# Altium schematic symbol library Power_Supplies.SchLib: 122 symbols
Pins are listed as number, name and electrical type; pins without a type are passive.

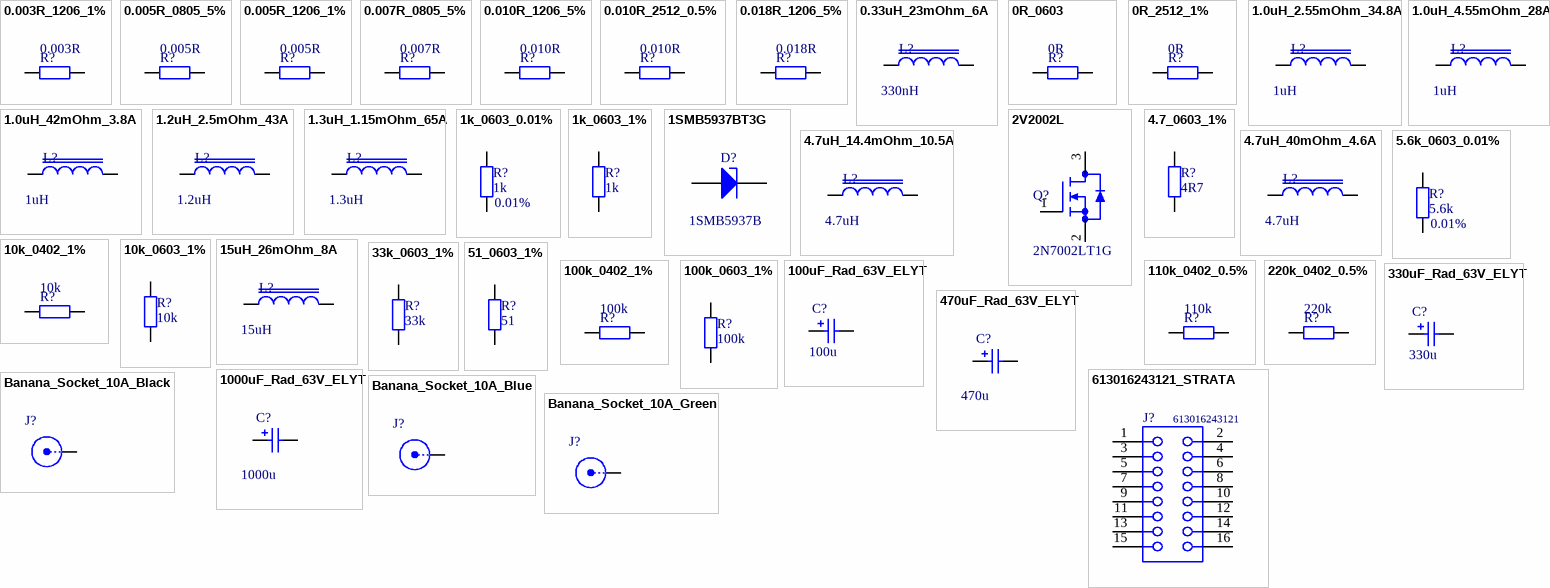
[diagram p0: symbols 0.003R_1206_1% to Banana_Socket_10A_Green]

## 0.003R_1206_1%
designator R?, comment value 0.003R  (hidden comment: WSL12063L000FEA18)
RES 0.003 OHM 1% 1/2W 1206, Vishay; Signature Author: Hukel; Value/Rating: 0.003R/1/2W; Substitution Allowed: Yes
footprint 1206_RES_MAX (1206, max dimensions from reflow soldering)
pins: 1, 2

## 0.005R_0805_5%
designator R?, comment value 0.005R  (hidden comment: ERJ-6LWJR005V)
RES 0.005 OHM 5% 1/2W 0805, Panasonic; Signature Author: Hukel; Value/Rating: 0.005R/1/2W; Substitution Allowed: Yes
footprint 0805_RES_MAX (0805, max dimensions from reflow soldering)
pins: 1, 2

## 0.005R_1206_1%
designator R?, comment value 0.005R  (hidden comment: WSL12065L000FEA18)
RES 0.005 OHM 1% 1/2W 1206, Vishay; Signature Author: Hukel; Value/Rating: 0.005R/1/2W; Substitution Allowed: Yes
footprint 1206_RES_MAX (1206, max dimensions from reflow soldering)
pins: 1, 2

## 0.007R_0805_5%
designator R?, comment value 0.007R  (hidden comment: ERJ-6LWJR007V)
RES 0.007 OHM 5% 1/2W 0805, Panasonic; Signature Author: Hukel; Value/Rating: 0.007R/1/2W; Substitution Allowed: Yes
footprint 0805_RES_MAX (0805, max dimensions from reflow soldering)
pins: 1, 2

## 0.010R_1206_5%
designator R?, comment value 0.010R  (hidden comment: ERJ-8CWJR010V)
RES 0.010 OHM 5% 1W 1206, Panasonic; Signature Author: Hukel; Value/Rating: 0.010R/1W; Substitution Allowed: Yes
footprint 1206_RES_MAX (1206, max dimensions from reflow soldering)
pins: 1, 2

## 0.010R_2512_0.5%
designator R?, comment value 0.010R  (hidden comment: PE2512DKM7W0R01L)
RES SMD 0.01 OHM 2W 2512; Yageo; Signature Author: Hukel; Rating: 1W; Tolerance: 0.5%; Value/Rating: 0.010R/1W; Substitution Allowed: Yes
footprint 2512_RES (2512, Reflow, YAGEO)
pins: 1, 2

## 0.018R_1206_5%
designator R?, comment value 0.018R  (hidden comment: ERJ-8CWJR018V)
RES 0.018 OHM 5% 1W 1206, Panasonic; Signature Author: Hukel; Value/Rating: 0.018R/1W; Substitution Allowed: Yes
footprint 1206_RES_MAX (1206, max dimensions from reflow soldering)
pins: 1, 2

## 0.33uH_23mOhm_6A
designator L?, comment value 330nH  (hidden comment: DFE252012PD-R33M)
0.33uH; 20%; 6A; 23mOhm; 2520; DFE252012PD-R33M; Murata; Signature Author: Hukel; Value/Rating: 330nH/6A; Substitution Allowed: Yes
footprint 2520_MURATA_IND_EVAL
pins: 1, 2

## 0R_0603
designator R?, comment value 0R  (hidden comment: Short)
RES SMD 0 OHM JUMPER 0603; Yageo; Signature Author: Hukel; Rating: 1W; Value/Rating: 0R/1W; Substitution Allowed: Yes
footprint 0603_RES (Chip Resistor, 2-Leads, Body 1.60x0.80mm, IPC Medium Density)
pins: 1, 2

## 0R_2512_1%
designator R?, comment value 0R  (hidden comment: RC2512JK-070RL)
RES SMD 0 OHM JUMPER 1W 2512; Yageo; Signature Author: Hukel; Value/Rating: 0R/1W; Substitution Allowed: Yes
footprint 0402_RES_MAX (0402, max dimensions from reflow soldering)
pins: 1, 2

## 1.0uH_2.55mOhm_34.8A
designator L?, comment value 1uH  (hidden comment: XAL7070-102MEC)
1.0uH; 20%; 34.8A; 2.55mOhm; 7.5x7.5x7mm ; XAL7070-102MEC; Coilcraft; Signature Author: Hukel; Value/Rating: 1uH/34.8A; Substitution Allowed: Yes
footprint XAL7070-102 (Precision Wire Wound Inductor, 2-Leads, Body 7.50x7.50mm, IPC Medium Density)
pins: 1, 2

## 1.0uH_4.55mOhm_28A
designator L?, comment value 1uH  (hidden comment: XAL7030-102MEC)
1.0uH; 20%; 28A; 4.55mOhm; 7.5x7.5x3.1mm ; XAL7030-102MEC; Coilcraft; Signature Author: Hukel; Value/Rating: 1uH/28A; Substitution Allowed: Yes
footprint XAL7030-102 (Precision Wire Wound Inductor, 2-Leads, Body 7.50x7.50mm, IPC Medium Density)
pins: 1, 2

## 1.0uH_42mOhm_3.8A
designator L?, comment value 1uH  (hidden comment: DFE252012PD-1R0M)
1.0uH; 20%; 3.8A; 42mOhm; 2520; DFE252012PD-1R0M; Murata; Signature Author: Hukel; Value/Rating: 1uH/3.8A; Substitution Allowed: Yes
footprint 2520_MURATA_IND_EVAL
pins: 1, 2

## 1.2uH_2.5mOhm_43A
designator L?, comment value 1.2uH  (hidden comment: XAL1060-122MED)
1.2uH; 20%; 43A; 2.50mOhm; 10x11.3x6mm ; XAL1060-122MED; Coilcraft; Signature Author: Hukel; Value/Rating: 1.2uH/43A; Substitution Allowed: Yes
footprint XAL1060-122 (XAL1060, Coilcraft)
pins: 1, 2

## 1.3uH_1.15mOhm_65A
designator L?, comment value 1.3uH  (hidden comment: XAL1580-132MEB)
1.3uH; 20%; 65A; 1.15mOhm; 15.2x16.2x8mm ; XAL1580-132MEB; Coilcraft; Signature Author: Hukel; Value/Rating: 1.3uH/65A; Substitution Allowed: Yes
footprint XAL1580-132
pins: 1, 2

## 1k_0603_0.01%
designator R?, comment value 1k  Tolerance: 0.01%  (hidden comment: PLT0603Z1001LBTS)
1k; 1/10W; 0.01%; 0603;  Vishay; Signature Author: Hukel; Value/Rating: 1k/1/10W; Substitution Allowed: Yes
simulation model RESISTOR (Resistor)
footprint 0603_RES (Chip Resistor, 2-Leads, Body 1.60x0.80mm, IPC Medium Density)
pins: 1, 2

## 1k_0603_1%
designator R?, comment value 1k  (hidden comment: RC0603FR-071KL)
1k; 1/10W; 1%; 0603; Yageo; Signature Author: Hukel; Value/Rating: 1k/1/10W; Substitution Allowed: Yes
simulation model RESISTOR (Resistor)
footprint 0603_RES (Chip Resistor, 2-Leads, Body 1.60x0.80mm, IPC Medium Density)
pins: 1, 2

## 1SMB5937BT3G
designator D?  value 1SMB5937B  (hidden comment: 1SMB5937BT3G)
1SMB5937B: 33 V, 3.0 W Zener Diode Voltage Regulator; SMB; ON Semiconductor; Signature Author: Hukel; Tolerance: 5%; Substitution Allowed: Yes; Rating: 33V/3W
footprint SMB (SMB, CASE403A-03, ISSUE J)
pins: 1 K, 2 A

## 2V2002L
designator Q?, comment 2N7002LT1G
60 V, 115 mA, 7.5 Ohm, N−Channel; SOT−23; ON Semiconductor; Signature Author: Hukel; Substitution Allowed: Yes
footprint SOT-23 (TO-236) (SOT-23 (TO-236), CASE 318-08, Issue AS)
pins: 1 G, 2 S, 3 D

## 4.7_0603_1%
designator R?, comment value 4R7  (hidden comment: RC0603FR-074R7L)
4.7; 1/10W; 1%; 0603; Yageo; Signature Author: Hukel; Value/Rating: 4R7/1/10W; Substitution Allowed: Yes
simulation model RESISTOR (Resistor)
footprint 0603_RES (Chip Resistor, 2-Leads, Body 1.60x0.80mm, IPC Medium Density)
pins: 1, 2

## 4.7uH_14.4mOhm_10.5A
designator L?, comment value 4.7uH  (hidden comment: XAL6060-472MEB)
4.7µH Shielded Wirewound Inductor 10.5A 14.4 mOhm Max; XAL6060-472MEB; Coilcraft; Signature Author: Hukel; Tolerance: ±20%; Value/Rating: 4.7uH/10.5A; Substitution Allowed: Yes
footprint XAL6060 (XAL6060 series Coilcraft inductors)
pins: 1, 2

## 4.7uH_40mOhm_4.6A
designator L?, comment value 4.7uH  (hidden comment: XEL4030-472MEB)
4.7µH Shielded Wirewound Inductor 4.6A 40 mOhm Max; XEL4030-472MEB; Coilcraft; Signature Author: Hukel; Tolerance: ±20%; Value/Rating: 4.7uH/4.6A; Substitution Allowed: Yes
footprint XEL4030 (XEL4030 series Colicraft inductors)
pins: 1, 2

## 5.6k_0603_0.01%
designator R?, comment value 5.6k  Tolerance: 0.01%  (hidden comment: PLT0603Z5621LBTS)
5.6k; 1/10W; 0.01%; 0603;  Vishay; Signature Author: Hukel; Value/Rating: 5.6k/1/10W; Substitution Allowed: Yes
simulation model RESISTOR (Resistor)
footprint 0603_RES (Chip Resistor, 2-Leads, Body 1.60x0.80mm, IPC Medium Density)
pins: 1, 2

## 10k_0402_1%
designator R?, comment value 10k  (hidden comment: RC0402FR-0710KL)
10k; 1/16W; 1%; 0402; Yageo; Signature Author: Hukel; Value/Rating: 10k/1/16W; Substitution Allowed: Yes
footprint 0402_RES_MAX (0402, max dimensions from reflow soldering)
pins: 1, 2

## 10k_0603_1%
designator R?, comment value 10k  (hidden comment: RC0603FR-0710KL)
10k; 1/10W; 1%; 0603; Yageo; Signature Author: Hukel; Value/Rating: 10k/1/10W; Substitution Allowed: Yes
simulation model RESISTOR (Resistor)
footprint 0603_RES (Chip Resistor, 2-Leads, Body 1.60x0.80mm, IPC Medium Density)
pins: 1, 2

## 15uH_26mOhm_8A
designator L?, comment value 15uH  (hidden comment: 7447709150)
15µH Shielded Wirewound Inductor 8A 26 mOhm Max; 7447709150; Wurth Electronics; Signature Author: Hukel; Tolerance: ±20%; Value/Rating: 15uH/8A; Substitution Allowed: Yes
footprint 1210_WE_IND (1210_WE_IND, Wuerth Inductor)
pins: 1, 2

## 33k_0603_1%
designator R?, comment value 33k  (hidden comment: RC0603FR-0733KL)
33k; 1/10W; 1%; 0603; Yageo; Signature Author: Hukel; Value/Rating: 33k/1/10W; Substitution Allowed: Yes
simulation model RESISTOR (Resistor)
footprint 0603_RES (Chip Resistor, 2-Leads, Body 1.60x0.80mm, IPC Medium Density)
pins: 1, 2

## 51_0603_1%
designator R?, comment value 51  (hidden comment: RC0603FR-0751RL)
51; 1/10W; 1%; 0603; Yageo; Signature Author: Hukel; Value/Rating: 51/1/10W; Substitution Allowed: Yes
simulation model RESISTOR (Resistor)
footprint 0603_RES (Chip Resistor, 2-Leads, Body 1.60x0.80mm, IPC Medium Density)
pins: 1, 2

## 100k_0402_1%
designator R?, comment value 100k  (hidden comment: RC0402FR-07100KL)
100k; 1/16W; 1%; 0402; Yageo; Signature Author: Hukel; Value/Rating: 100k/1/16W; Substitution Allowed: Yes
footprint 0402_RES (0402, Reflow, YAGEO)
pins: 1, 2

## 100k_0603_1%
designator R?, comment value 100k  (hidden comment: RC0603FR-07100KL)
100k; 1/10W; 1%; 0603; Yageo; Signature Author: Hukel; Value/Rating: 100k/1/10W; Substitution Allowed: Yes
simulation model RESISTOR (Resistor)
footprint 0603_RES (Chip Resistor, 2-Leads, Body 1.60x0.80mm, IPC Medium Density)
pins: 1, 2

## 100uF_Rad_63V_ELYT
designator C?, comment value 100u  (hidden comment: EEUFR1J101B)
100uF; 63 V; 20%; EEUFR1J101B; Panasonic; Signature Author: Zemanovic; Rating: 63V; Value/Rating: 100u/63V; Substitution Allowed: Yes
footprint Elyt_Radial_10X12.5 (Electrolytic Radial Aluminium capacitor 10 x 12.5 mm)
pins: 1, 2
1 alternate drawing of the same symbol

## 110k_0402_0.5%
designator R?, comment value 110k  (hidden comment: RC0402DR-07110KL)
110k; 1/16W; 0.5%; 0402; Yageo; Signature Author: Hukel; Value/Rating: 110k/1/16W; Substitution Allowed: Yes
footprint 0402_RES (0402, Reflow, YAGEO)
pins: 1, 2

## 220k_0402_0.5%
designator R?, comment value 220k  (hidden comment: RC0402DR-07220KL)
220k; 1/16W; 0.5%; 0402; Yageo; Signature Author: Hukel; Value/Rating: 220k/1/16W; Substitution Allowed: Yes
footprint 0402_RES_MAX (0402, max dimensions from reflow soldering)
pins: 1, 2

## 330uF_Rad_63V_ELYT
designator C?, comment value 330u  (hidden comment: EEUFR1J331B)
330uF; 63 V; 20%; EEUFR1J331B; Panasonic; Signature Author: Nagy; Rating: 63V; Value/Rating: 330u/63V; Substitution Allowed: Yes
footprint Elyt_Radial_10X12.5 (Electrolytic Radial Aluminium capacitor 10 x 12.5 mm)
pins: 1, 2
1 alternate drawing of the same symbol

## 470uF_Rad_63V_ELYT
designator C?, comment value 470u  (hidden comment: EUFR1J471)
470uF; 63V; 20%; ELYT; EUFR1J471; Panasonic; Signature Author: Zemanovic; Value/Rating: 470u/63V; Substitution Allowed: Yes
footprint Axial_D12.5_Pol
pins: 1, 2
1 alternate drawing of the same symbol

## 1000uF_Rad_63V_ELYT
designator C?, comment value 1000u  (hidden comment: EEU-FC1J102U)
1000uF; 63V; 20%; ELYT; EEU-FC1J102U; Panasonic; Signature Author: Nagy; Value/Rating: 1000u/63V; Substitution Allowed: Yes
footprint ELYT_RADIAL_16x31.5
pins: 1, 2
1 alternate drawing of the same symbol

## 613016243121_STRATA
designator J?, comment 613016243121
THT Angled Socket Header WR-PHD, Pitch 2.54 mm, Dual Row, 16 pins; Manufacturer: WUERTH ELECTRONIC; Pin Number: 16; Pitch: 2.54 mm; Gender: Female; Rated Current: 3 A; Working Voltage: 250 VAC; Withstanding Voltage: 500 VAC; Contact Resistance: 20 mOhm; Substitution Allowed: Yes; Signature Author: Hukel
footprint 613016243121_Strata (Socket Header, Pitch 2.54 mm, THT, Angled, dual row, 16p)
pins: 1, 2, 3, 4, 5, 6, 7, 8, 9, 10, 11, 12, 13, 14, 15, 16

## Banana_Socket_10A_Black
designator J?, comment 571-0100-01  (value not drawn)
10A; 4mm; TH; Black; 571-0100-01 ; DELTRON; Signature Author: Nagy; Substitution Allowed: Yes
footprint PCB Jack 4mm - black (DELTRON 571-0100-01)
pins: 1

## Banana_Socket_10A_Blue
designator J?, comment 571-0200-01  (value not drawn)
10A; 4mm; TH; Blue; 571-0200-01 ; DELTRON; Signature Author: Nagy; Substitution Allowed: Yes
footprint PCB Jack 4mm - blue (DELTRON 571-0200-01)
pins: 1

## Banana_Socket_10A_Green
designator J?, comment 571-0400-01  (value not drawn)
10A; 4mm; TH; Green; 571-0400-01 ; DELTRON; Signature Author: Nagy; Substitution Allowed: Yes
footprint PCB Jack 4mm - green (DELTRON 571-0400-01)
pins: 1

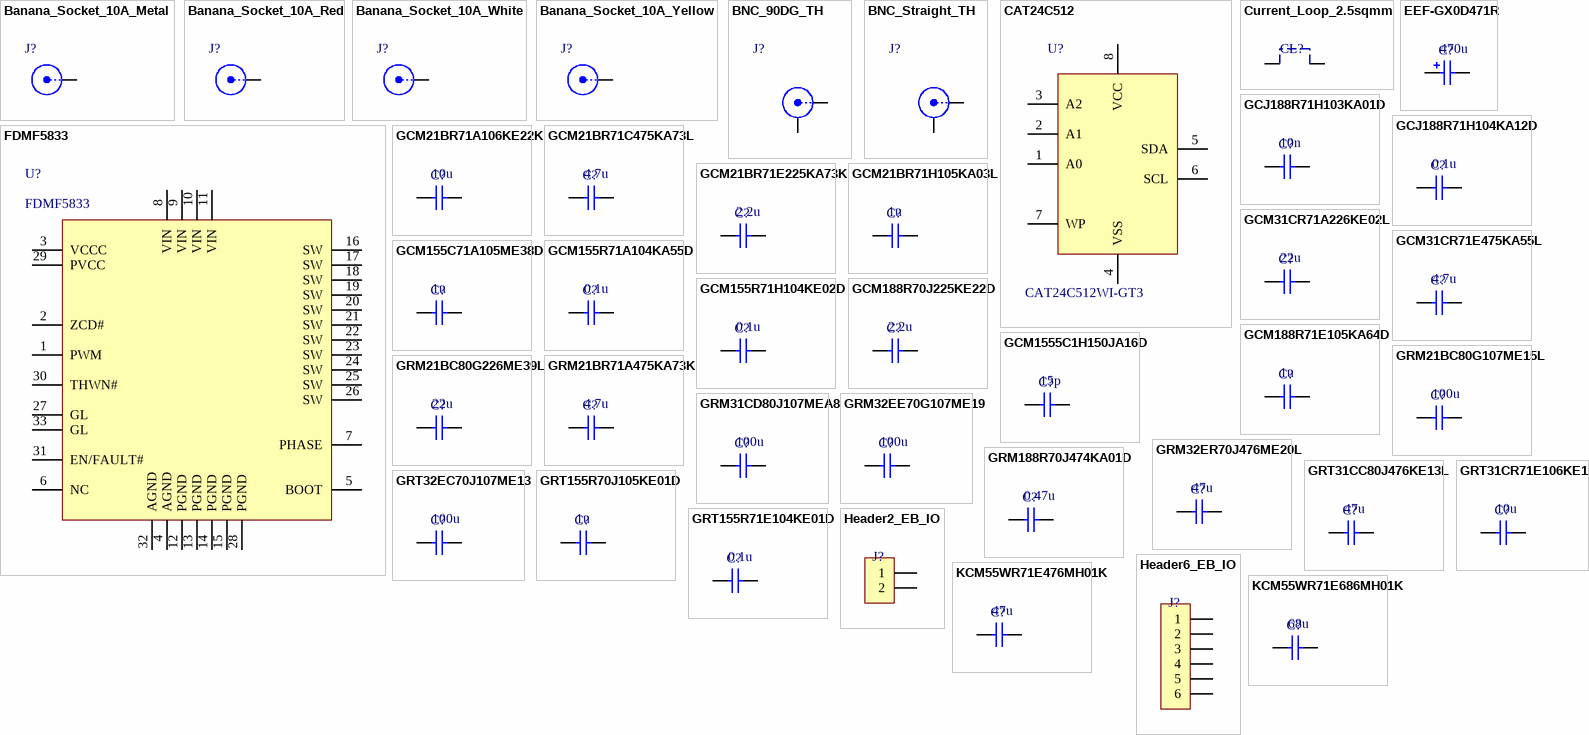
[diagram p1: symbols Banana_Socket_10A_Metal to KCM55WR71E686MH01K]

## Banana_Socket_10A_Metal
designator J?, comment SPC15459  (value not drawn)
10A; 4mm; TH; Metal; SPC15459 ; MULTICOMP; Signature Author: Nagy; Substitution Allowed: Yes
footprint PCB Banana - 1
pins: 1

## Banana_Socket_10A_Red
designator J?, comment 571-0500-01  (value not drawn)
10A; 4mm; TH; Red; 571-0500-01 ; DELTRON; Signature Author: Nagy; Substitution Allowed: Yes
footprint PCB Jack 4mm - red (DELTRON 571-0500-01)
pins: 1

## Banana_Socket_10A_White
designator J?, comment 571-0600-01  (value not drawn)
10A; 4mm; TH; White; 571-0600-01 ; DELTRON; Signature Author: Nagy; Substitution Allowed: Yes
footprint PCB Jack 4mm - white (DELTRON 571-0600-01)
pins: 1

## Banana_Socket_10A_Yellow
designator J?, comment 571-0700-01  (value not drawn)
10A; 4mm; TH; Yellow; 571-0700-01 ; DELTRON; Signature Author: Nagy; Substitution Allowed: Yes
footprint PCB Jack 4mm - yellow (DELTRON 571-0700-01)
pins: 1

## BNC_90DG_TH
designator J?, comment B6252HB-NPP3G-50  (value not drawn)
BNC 90 Angle Connector; 1.5GHz; B6252HB-NPP3G-50; Amphenol; Signature Author: Zemanovic; Substitution Allowed: Yes
footprint BNC_90DG_TH
pins: 1, 2

## BNC_Straight_TH
designator J?, comment R141426161  (value not drawn)
BNC Straight Connector; 1.5GHz; R141426161; Radial; Manufacturer: Radiall; Signature Author: Zemanovic; Substitution Allowed: Yes
footprint BNC_connector_Through_Hole_Vertical
pins: 1, 2

## CAT24C512
designator U?  value CAT24C512WI-GT3  (hidden comment: CAT24C512)
EEPROM Serial 512-Kb I2C; SO-8; ON Semiconductor; Signature Author: Hukel; Substitution Allowed: No
footprint SOIC-8 (SOIC-8 NB, CASE 751-7, Issue AK)
pins: 1 A0, 2 A1, 3 A2, 4 VSS, 5 SDA, 6 SCL, 7 WP, 8 VCC

## Current_Loop_2.5sqmm
designator CL?, comment Current Loop for 2.5 sqmm Cu wire  (value not drawn)
Current Loop Wire for Osciloscope Current Probe; Signature Author: Hukel; Rating: 1W; Tolerance: Wire Loop; Value/Rating: 0.005/1W; Substitution Allowed: Yes; Value: 0.005
footprint Current_Loop_2.5sqmm
pins: 1, 2

## EEF-GX0D471R
designator C?  value 470u  (hidden comment: EEF-GX0D471R)
470uF; 2V; Polymer Aluminum; 20%; 7343; EEF-GX0D471R; Panasonic; Signature Author: Hukel; Substitution Allowed: Yes; Value/Rating: 470u/2V
footprint 7343-20 (7343-20, Polymer Aluminum Electrolytic Capacitors, GX Series, ody 7.3x4.3x1.9 mm)
pins: 1, 2

## FDMF5833
designator U?
Smart Power Stage (SPS) Module with Integrated Thermal Warning and Thermal Shutdown
footprint PQFN31 5x5, 0.5P (DrMOS)
pins: 1 PWM, 2 ZCD#, 3 VCCC, 4 AGND, 5 BOOT, 6 NC, 7 PHASE, 8 VIN, 9 VIN, 10 VIN, 11 VIN, 12 PGND, 13 PGND, 14 PGND, 15 PGND, 16 SW, 17 SW, 18 SW, 19 SW, 20 SW, 21 SW, 22 SW, 23 SW, 24 SW, 25 SW, 26 SW, 27 GL, 28 PGND, 29 PVCC, 30 THWN#, 31 EN/FAULT#, 32 AGND, 33 GL

## GCJ188R71H103KA01D
designator C?  value 10n  (hidden comment: GCJ188R71H103KA01D)
10nF; 50V; X7R; 10%; 0603; GCJ188R71H103KA01D; Murata; Signature Author: Hukel; Substitution Allowed: Yes; Value/Rating: 10n/50V
footprint 0603_CAP (0603, MLCC, GRT Series, middle dimensions from reflow soldering, +/-0.15/+/-0.20 tolerances)
footprint 0603_CAP_MAX (0603, MLCC, GCM Series, max dimensions from reflow soldering)
pins: 1, 2

## GCJ188R71H104KA12D
designator C?  value 0.1u  (hidden comment: GCJ188R71H104KA12D)
0.1uF; 50V; X7R; 10%; 0603; GRM188R70J474KA01D; Murata; Signature Author: Hukel; Substitution Allowed: Yes; Value/Rating: 0.1u/50V
footprint 0603_CAP (0603, MLCC, GRT Series, middle dimensions from reflow soldering, +/-0.15/+/-0.20 tolerances)
footprint 0603_CAP_MAX (0603, MLCC, GCM Series, max dimensions from reflow soldering)
pins: 1, 2

## GCM21BR71A106KE22K
designator C?  value 10u  (hidden comment: GCM21BR71A106KE22K)
10uF; 10V; X7R; 10%; 0805; GCM21BR71A106KE22K; Murata; Signature Author: Hukel; Substitution Allowed: Yes; Value/Rating: 10u/10V
footprint 0805_CAP_MAX (0805, MLCC, GCM Series, max dimensions from reflow soldering)
pins: 1, 2

## GCM21BR71C475KA73L
designator C?  value 4.7u  (hidden comment: GCM21BR71C475KA73L)
4.7uF; 10V; X7R; 10%; 0805; GCM21BR71C475KA73L; Murata; Signature Author: Hukel; Substitution Allowed: Yes; Value/Rating: 4.7u/10V
footprint 0805_CAP_MAX (0805, MLCC, GCM Series, max dimensions from reflow soldering)
pins: 1, 2

## GCM21BR71E225KA73K
designator C?  value 2.2u  (hidden comment: GCM21BR71E225KA73K)
2.2uF; 25V; X7R; 10%; 0805; GCM21BR71E225KA73KL; Murata; Signature Author: Hukel; Substitution Allowed: Yes; Value/Rating: 2.2u/25V
footprint 0805_CAP_MAX (0805, MLCC, GCM Series, max dimensions from reflow soldering)
footprint 0805_CAP (0805, MLCC, GRT Series, middle dimensions from reflow soldering, +/-0.20 tolerances)
pins: 1, 2

## GCM21BR71H105KA03L
designator C?  value 1u  (hidden comment: GCM21BR71H105KA03L)
1uF; 50V; X7R; 10%; 0805; GCM21BR71H105KA03L; Murata; Signature Author: Hukel; Substitution Allowed: Yes; Value/Rating: 1u/50V
footprint 0805_CAP_MAX (0805, MLCC, GCM Series, max dimensions from reflow soldering)
footprint 0805_CAP (0805, MLCC, GRT Series, middle dimensions from reflow soldering, +/-0.20 tolerances)
pins: 1, 2

## GCM31CR71A226KE02L
designator C?  value 22u  (hidden comment: GCM31CR71A226KE02L)
22uF; 10V; X7R; 10%; 1206; GCM31CR71A226KE02L; Murata; Signature Author: Hukel; Substitution Allowed: Yes; Value/Rating: 22u/10V
footprint 1206_CAP_MAX (1206, MLCC, GCM Series, max dimensions from reflow soldering)
pins: 1, 2

## GCM31CR71E475KA55L
designator C?  value 4.7u  (hidden comment: GCM31CR71E475KA55L)
4.7uF; 25V; X7R; 10%; 1206; GCM31CR71E475KA55L; Murata; Signature Author: Hukel; Substitution Allowed: Yes; Value/Rating: 4.7u/25V
footprint 1206_CAP_MAX (1206, MLCC, GCM Series, max dimensions from reflow soldering)
pins: 1, 2

## GCM155C71A105ME38D
designator C?  value 1u  (hidden comment: GCM155C71A105ME38D)
1uF; 10V; X7S; 20%; 0402; GCM155C71A105ME38D; Murata; Signature Author: Hukel; Substitution Allowed: Yes; Value/Rating: 1u/10V
footprint 0402_CAP_MAX (0402, MLCC, GCM Series, max dimensions from reflow soldering)
footprint 0402_CAP (0402, MLCC, GRT Series, middle dimensions from reflow soldering, +/-0.15/+/-0.20 tolerances)
pins: 1, 2

## GCM155R71A104KA55D
designator C?  value 0.1u  (hidden comment: GCM155R71A104KA55D)
0.1uF; 10V; X7R; 10%; 0402; GCM155R71A104KA55D; Murata; Signature Author: Hukel; Substitution Allowed: Yes; Value/Rating: 0.1u/10V
footprint 0402_CAP_MAX (0402, MLCC, GCM Series, max dimensions from reflow soldering)
footprint 0402_CAP (0402, MLCC, GRT Series, middle dimensions from reflow soldering, +/-0.15/+/-0.20 tolerances)
pins: 1, 2

## GCM155R71H104KE02D
designator C?  value 0.1u  (hidden comment: GCM155R71H104KE02D)
0.1uF; 50V; X7R; 10%; 0402; GCM155R71H104KE02D; Murata; Signature Author: Hukel; Substitution Allowed: Yes; Value/Rating: 0.1u/50V
footprint 0402_CAP_MAX (0402, MLCC, GCM Series, max dimensions from reflow soldering)
footprint 0402_CAP (0402, MLCC, GRT Series, middle dimensions from reflow soldering, +/-0.15/+/-0.20 tolerances)
pins: 1, 2

## GCM188R70J225KE22D
designator C?  value 2.2u  (hidden comment: GCM188R70J225KE22D)
2.2uF; 6.3V; X7R; 10%; 0603; GCM188R70J225KE22D; Murata; Signature Author: Hukel; Substitution Allowed: Yes; Value/Rating: 2.2u/6.3V
footprint 0603_CAP_MAX (0603, MLCC, GCM Series, max dimensions from reflow soldering)
footprint 0603_CAP (0603, MLCC, GRT Series, middle dimensions from reflow soldering, +/-0.15/+/-0.20 tolerances)
pins: 1, 2

## GCM188R71E105KA64D
designator C?  value 1u  (hidden comment: GCM188R71E105KA64D)
1uF; 25V; X7R; 10%; 0603; GCM188R71E105KA64D; Murata; Signature Author: Hukel; Substitution Allowed: Yes; Value/Rating: 1u/25V
footprint 0603_CAP_MAX (0603, MLCC, GCM Series, max dimensions from reflow soldering)
footprint 0603_CAP (0603, MLCC, GRT Series, middle dimensions from reflow soldering, +/-0.15/+/-0.20 tolerances)
pins: 1, 2

## GCM1555C1H150JA16D
designator C?  value 15p  (hidden comment: GCM1555C1H150JA16D)
15pF; 50V; C0G; 5%; 0402; GCM1555C1H150JA16D; Murata; Signature Author: Hukel; Substitution Allowed: Yes; Value/Rating: 15p/50V
footprint 0402_CAP_MAX (0402, MLCC, GCM Series, max dimensions from reflow soldering)
footprint 0402_CAP (0402, MLCC, GRT Series, middle dimensions from reflow soldering, +/-0.15/+/-0.20 tolerances)
pins: 1, 2

## GRM21BC80G107ME15L
designator C?  value 100u  (hidden comment: GRM21BC80G107ME15L)
100uF; 4V; X6S; 20%; 0805; GRM21BC80G107ME15L; Murata; Signature Author: Hukel; Substitution Allowed: Yes; Value/Rating: 100u/4V
footprint 0805_CAP_MAX (0805, MLCC, GCM Series, max dimensions from reflow soldering)
footprint 0805_CAP (0805, MLCC, GRT Series, middle dimensions from reflow soldering, +/-0.20 tolerances)
pins: 1, 2

## GRM21BC80G226ME39L
designator C?  value 22u  (hidden comment: GRM21BC80G226ME39L)
22uF; 4V; X6S; 20%; 0805; GRM21BC80G226ME39L; Murata; Signature Author: Hukel; Substitution Allowed: Yes; Value/Rating: 22u/4V
footprint 0805_CAP_MAX (0805, MLCC, GCM Series, max dimensions from reflow soldering)
footprint 0805_CAP (0805, MLCC, GRT Series, middle dimensions from reflow soldering, +/-0.20 tolerances)
pins: 1, 2

## GRM21BR71A475KA73K
designator C?  value 4.7u  (hidden comment: GRM21BR71A475KA73K)
4.7uF; 10V; X7R; 10%; 0805; GRM21BR71A475KA73K;Murata; Signature Author: Hukel; Substitution Allowed: Yes; Value/Rating: 4.7u/10V
footprint 0805_CAP
pins: 1, 2

## GRM31CD80J107MEA8
designator C?  value 100u  (hidden comment: GRM31CD80J107MEA8)
100uF; 6.3V; X6T; 20%; 1206; GRM31CD80J107MEA8; Murata; Signature Author: Hukel; Substitution Allowed: Yes; Value/Rating: 100u/6.3V
footprint 1206_CAP_MAX (1206, MLCC, GCM Series, max dimensions from reflow soldering)
footprint 1206_CAP (1206_CAP, MLCC, GRT Series, middle dimensions from reflow soldering, +/-0.20 tolerances)
pins: 1, 2

## GRM32EE70G107ME19
designator C?  value 100u  (hidden comment: GRM32EE70G107ME19)
100uF; 4V; X7U; 20%; 1210; GRM32EE70G107ME19; Murata; Signature Author: Hukel; Substitution Allowed: Yes; Value/Rating: 100u/4V
footprint 1210_CAP (1210_CAP, MLCC, GRT Series, middle dimensions from reflow soldering, +/-0.20 tolerances)
pins: 1, 2

## GRM32ER70J476ME20L
designator C?  value 47u  (hidden comment: GRM32ER70J476ME20L)
47uF; 6.3V; X7R; 20%; 1210; GRM32ER70J476ME20L; Murata; Signature Author: Hukel; Substitution Allowed: Yes; Value/Rating: 47u/6.3V
footprint 1210_CAP (1210_CAP, MLCC, GRT Series, middle dimensions from reflow soldering, +/-0.20 tolerances)
pins: 1, 2

## GRM188R70J474KA01D
designator C?  value 0.47u  (hidden comment: GRM188R70J474KA01D)
0.47uF; 6.3V; X7R; 10%; 0603; GRM188R70J474KA01D; Murata; Signature Author: Hukel; Substitution Allowed: Yes; Value/Rating: 0.47u/6.3V
footprint 0603_CAP (0603, MLCC, GRT Series, middle dimensions from reflow soldering, +/-0.15/+/-0.20 tolerances)
footprint 0603_CAP_MAX (0603, MLCC, GCM Series, max dimensions from reflow soldering)
pins: 1, 2

## GRT31CC80J476KE13L
designator C?  value 47u  (hidden comment: GRT31CC80J476KE13L)
47uF; 6.3V; X6S; 10%; 1206; GRT31CC80J476KE13L; Murata; Signature Author: Hukel; Substitution Allowed: Yes; Value/Rating: 47u/6.3V
footprint 1206_CAP_MAX (1206, MLCC, GCM Series, max dimensions from reflow soldering)
footprint 1206_CAP (1206_CAP, MLCC, GRT Series, middle dimensions from reflow soldering, +/-0.20 tolerances)
pins: 1, 2

## GRT31CR71E106KE13
designator C?  value 10u  (hidden comment: GRT31CR71E106KE13)
10uF; 25V; X7R; 10%; 1206; GRT31CR71E106KE13; Murata; Signature Author: Hukel; Substitution Allowed: Yes; Value/Rating: 10u/25V
footprint 1206_CAP (1206_CAP, MLCC, GRT Series, middle dimensions from reflow soldering, +/-0.20 tolerances)
pins: 1, 2

## GRT32EC70J107ME13
designator C?  value 100u  (hidden comment: GRT32EC70J107ME13)
100uF; 6.3V; X7S; 20%; 1210; GRT32EC70J107ME13; Murata; Signature Author: Hukel; Substitution Allowed: Yes; Value/Rating: 100u/6.3V
footprint 1210_CAP (1210_CAP, MLCC, GRT Series, middle dimensions from reflow soldering, +/-0.20 tolerances)
footprint 1210_CAP_MAX (1210, MLCC, GCM Series, max dimensions from reflow soldering)
pins: 1, 2

## GRT155R70J105KE01D
designator C?  value 1u  (hidden comment: GRT155R70J105KE01D)
1uF; 6.3V; X7R; 10%; 0402; GRT155R70J105KE01D; Murata; Signature Author: Hukel; Substitution Allowed: Yes; Value/Rating: 1u/6.3V
footprint 0402_CAP_MAX (0402, MLCC, GCM Series, max dimensions from reflow soldering)
footprint 0402_CAP (0402, MLCC, GRT Series, middle dimensions from reflow soldering, +/-0.15/+/-0.20 tolerances)
pins: 1, 2

## GRT155R71E104KE01D
designator C?  value 0.1u  (hidden comment: GRT155R71E104KE01D)
0.1uF; 25V; X7R; 10%; 0402; GRT155R71E104KE01D; Murata; Signature Author: Hukel; Substitution Allowed: Yes; Value/Rating: 0.1u/25V
footprint 0402_CAP_MAX (0402, MLCC, GCM Series, max dimensions from reflow soldering)
footprint 0402_CAP (0402, MLCC, GRT Series, middle dimensions from reflow soldering, +/-0.15/+/-0.20 tolerances)
pins: 1, 2

## Header2_EB_IO
designator J?, comment TSW-102-07-G-S  (value not drawn)
Board-To-Board Connector; Header 1x2; TSW Series;  Samtec; Signature Author: Zemanovic; Substitution Allowed: Yes
footprint Header_2
pins: 1, 2

## Header6_EB_IO
designator J?, comment 22-28-4360  (value not drawn)
Board-To-Board Connector; Header; 36;  22-28-4360; Manufacturer: Molex; Signature Author: Nagy; Substitution Allowed: Yes
footprint Header_6
pins: 1, 2, 3, 4, 5, 6

## KCM55WR71E476MH01K
designator C?  value 47u  (hidden comment: KCM55WR71E476MH01K)
47uF; 25V; X7R; 20%; 2220; KCM55WR71E476MH01K1; Murata; Signature Author: Hukel; Substitution Allowed: Yes; Value/Rating: 47u/25V
footprint 2220_KCM55 (Chip Capacitor, 2-Leads, Body 6.1x5.3x3.7mm, IPC Medium Density)
pins: 1, 2

## KCM55WR71E686MH01K
designator C?  value 68u  (hidden comment: KCM55WR71E686MH01K)
68uF; 25V; X7R; 20%; 2220; KCM55WR71E686MH01K; Murata; Signature Author: Hukel; Substitution Allowed: Yes; Value/Rating: 68u/25V
footprint 2220_KCM55 (Chip Capacitor, 2-Leads, Body 6.1x5.3x3.7mm, IPC Medium Density)
pins: 1, 2

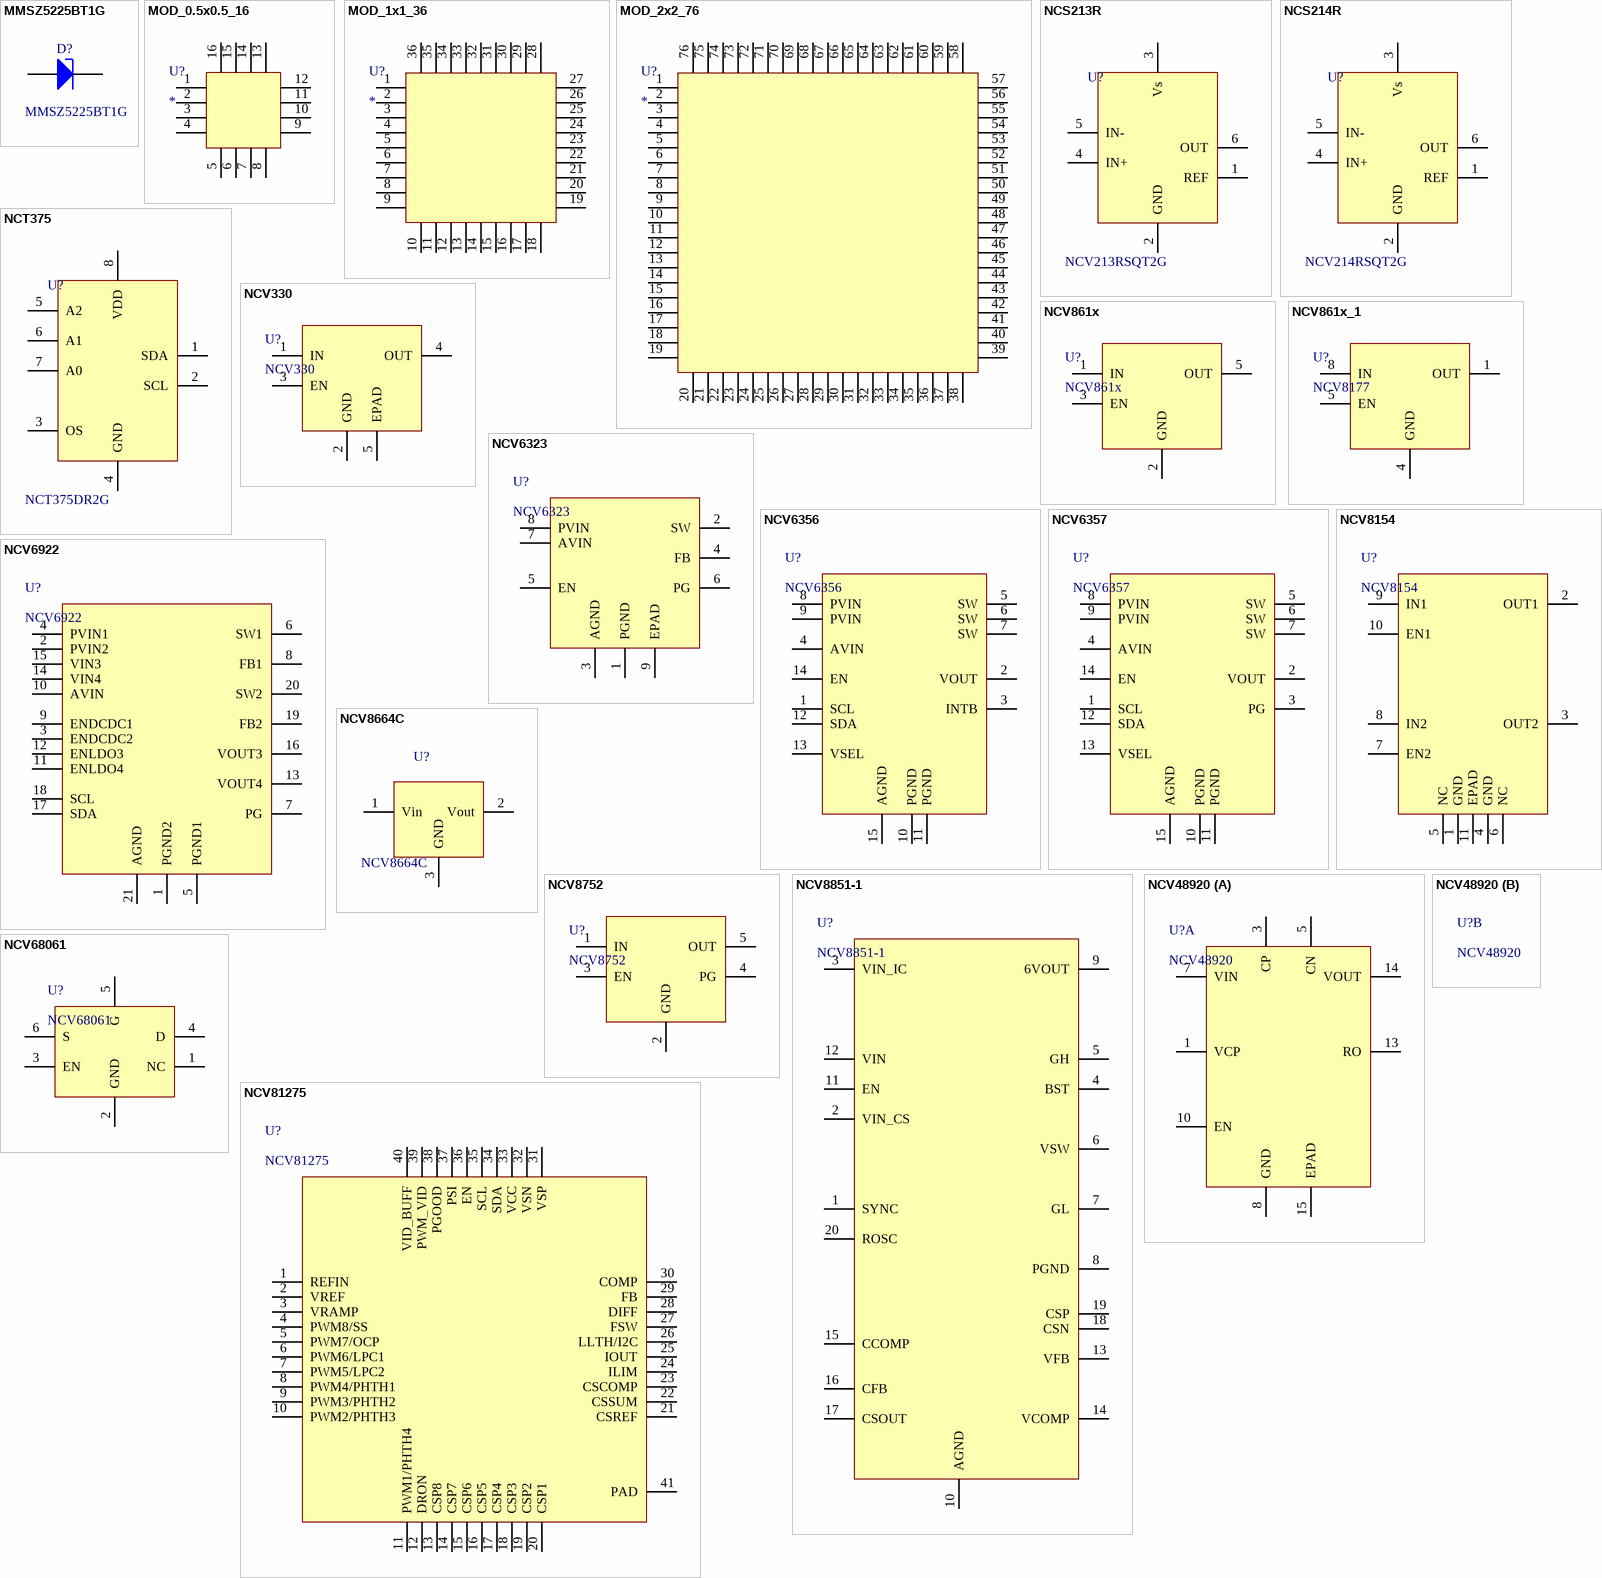
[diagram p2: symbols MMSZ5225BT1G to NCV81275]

## MMSZ5225BT1G
designator D?
MMSZ52xxxT1G; 3.0V/0.5W; SOD-123; ON Semiconductor; Signature Author: Nagy; Tolerance: 5%; Substitution Allowed: Yes
footprint SOD-123 (SOD, 2-Leads, Body 2.69x1.6mm)
pins: 1 K, 2 A

## MOD_0.5x0.5_16
designator U?
PCB Footprint for 0.5 x 0.5 inch PCB Module; Substitution Allowed: No
footprint MOD_0.5x0.5_16
pins: 1, 2, 3, 4, 5, 6, 7, 8, 9, 10, 11, 12, 13, 14, 15, 16

## MOD_1x1_36
designator U?
PCB Footprint for 1 x 1 inch PCB Module; Substitution Allowed: No
footprint MOD_1x1_36
pins: 1, 2, 3, 4, 5, 6, 7, 8, 9, 10, 11, 12, 13, 14, 15, 16, 17, 18, 19, 20, 21, 22, 23, 24, 25, 26, 27, 28, 29, 30, 31, 32, 33, 34, 35, 36

## MOD_2x2_76
designator U?
PCB Footprint for 2 x 2 inch PCB Module; Substitution Allowed: No
footprint MOD_2x2_76
pins: 1, 2, 3, 4, 5, 6, 7, 8, 9, 10, 11, 12, 13, 14, 15, 16, 17, 18, 19, 20, 21, 22, 23, 24, 25, 26, 27, 28, 29, 30, 31, 32, 33, 34, 35, 36, 37, 38, 39, 40, 41, 42, 43, 44, 45, 46, 47, 48, 49, 50, 51, 52, 53, 54, 55, 56, 57, 58, 59, 60, 61, 62, 63, 64, 65, 66, 67, 68, 69, 70, 71, 72, 73, 74, 75, 76

## NCS213R
designator U?  value NCV213RSQT2G  (hidden comment: NCS213R)
Current-Shunt Monitors, Voltage Output, Bidirectional Zero-Drift, Low- or High-Side Current Sensing; SO-8; ON Semiconductor; Signature Author: Hukel; Substitution Allowed: No
footprint SC-88/SC70-6/SOT-363 (SC-88/SC70-6/SOT-363, CASE 419B-02, Issue Y)
pins: 1 REF, 2 GND, 3 Vs, 4 IN+, 5 IN-, 6 OUT

## NCS214R
designator U?  value NCV214RSQT2G  (hidden comment: NCS214R)
Current-Shunt Monitors, Voltage Output, Bidirectional Zero-Drift, Low- or High-Side Current Sensing; SO-8; ON Semiconductor; Signature Author: Hukel; Substitution Allowed: No
footprint SC-88/SC70-6/SOT-363 (SC-88/SC70-6/SOT-363, CASE 419B-02, Issue Y)
pins: 1 REF, 2 GND, 3 Vs, 4 IN+, 5 IN-, 6 OUT

## NCT375
designator U?  value NCT375DR2G  (hidden comment: NCT375)
Industry Standard Digital Temperature Sensor with / 2‐wire Interface; SO-8; ON Semiconductor; Signature Author: Hukel; Substitution Allowed: No
footprint SOIC-8 (SOIC-8 NB, CASE 751-7, Issue AK)
pins: 1 SDA, 2 SCL, 3 OS, 4 GND, 5 A2, 6 A1, 7 A0, 8 VDD

## NCV330
designator U?
NCV330 Soft-Start Controlled Load Switch
footprint UDFN4 1.2x1.6, 0.5P (UDFN4 1.2x1.6, 0.5P, CASE 517CE, Issue B)
pins: 1 IN, 2 GND, 3 EN, 4 OUT, 5 EPAD

## NCV861x
designator U?
NCV861x Family of Low Dropout Regulators
footprint TSOP-5 (TSOP, 5-Leads, Body 3.00x1.50mm, Pitch 0.95mm, IPC Medium Density)
pins: 1 IN, 2 GND, 3 EN, 5 OUT

## NCV861x_1
designator U?, comment NCV8177
NCV8177 Linear Voltage Regulator Fast Transient Response 500 mA with Enable
footprint WDFNW8 2x2, 0.5P (WDFNW8 2x2, 0.5P, CASE 511CL, Issue O)
pins: 1 OUT, 4 GND, 5 EN, 8 IN

## NCV6323
designator U?
3 MHz, 2 A Synchronous Buck Converter
footprint WDFNW8 2x2, 0.5P (WDFNW8 2x2, 0.5P, CASE 511CL, Issue O)
pins: 1 PGND, 2 SW, 3 AGND, 4 FB, 5 EN, 6 PG, 7 AVIN, 8 PVIN, 9 EPAD

## NCV6356
designator U?
Configurable 5.0 A AOT Step Down Converter
footprint WDFNW14 4x3, 0.5P (WDFNW14 4x3, 0.5P, CASE 511CM, Issue A)
pins: 1 SCL, 2 VOUT, 3 INTB, 4 AVIN, 5 SW, 6 SW, 7 SW, 8 PVIN, 9 PVIN, 10 PGND, 11 PGND, 12 SDA, 13 VSEL, 14 EN, 15 AGND "EPAD"

## NCV6357
designator U?
Configurable 5.0 A AOT Step Down Converter
footprint WDFNW14 4x3, 0.5P (WDFNW14 4x3, 0.5P, CASE 511CM, Issue A)
pins: 1 SCL, 2 VOUT, 3 PG "INTB", 4 AVIN, 5 SW, 6 SW, 7 SW, 8 PVIN, 9 PVIN, 10 PGND, 11 PGND, 12 SDA, 13 VSEL, 14 EN, 15 AGND "EPAD"

## NCV6922
designator U?
4 Channels PMIC with 2 DC-to-DC Converters and 2 LDOs
footprint QFNW20 4x4, 0.5P (QFNW20 4x4, 0.5P, CASE 484AD, Issue B)
pins: 1 PGND2, 2 PVIN2, 3 ENDCDC2, 4 PVIN1, 5 PGND1, 6 SW1, 7 PG, 8 FB1, 9 ENDCDC1, 10 AVIN, 11 ENLDO4, 12 ENLDO3, 13 VOUT4, 14 VIN4, 15 VIN3, 16 VOUT3, 17 SDA, 18 SCL, 19 FB2, 20 SW2, 21 AGND

## NCV8154
designator U?
Dual 300 mA, Low IQ, Low Dropout, Dual Input Voltage Regulator
footprint DFN10 3x3, 0.5P (DFN10 3x3, 0.5P, CASE 507AG, Issue A)
pins: 1 GND, 2 OUT1, 3 OUT2, 4 GND, 5 NC, 6 NC, 7 EN2, 8 IN2, 9 IN1, 10 EN1, 11 EPAD

## NCV8664C
designator U?, comment value NCV8664C  (hidden comment: NCV8664CDT50)
NCV8664C; 5V/150mA, 2.0% Very Low Iq, Low Dropout Linear Regulator; DPAK-3; ON Semiconductor; Signature Author: Hukel; Substitution Allowed: No
footprint DPAK-3_L (D-PAK, 3-Pads, Body 8.31x6.73mm (max), IPC Low Density)
pins: 1 Vin, 2 Vout, 3 GND

## NCV8752
designator U?
200 mA, Ultra-Low Quiescent Current, IQ 12 uA, Ultra-Low Noise, Low Dropout Regulator
footprint XDFN6 1.5x1.5, 0.5P
pins: 1 IN, 2 GND, 3 EN, 4 PG, 5 OUT

## NCV8851-1
designator U?
Automotive Grade Synchronous Buck Controller
footprint TSSOP-20 (TSSOP, 20-Leads, Body 6.50x4.40mm, Pitch 0.65mm, IPC Medium Density)
pins: 1 SYNC, 2 VIN_CS, 3 VIN_IC, 4 BST, 5 GH, 6 VSW, 7 GL, 8 PGND, 9 6VOUT, 10 AGND, 11 EN, 12 VIN, 13 VFB, 14 VCOMP, 15 CCOMP, 16 CFB, 17 CSOUT, 18 CSN, 19 CSP, 20 ROSC

## NCV48920
designator U?
600 mA Buck/ 300 mA Noost Charge Pump Regulator for Automotive
footprint TSSOP-14-EP (SOP, 14-Leads Exposed PAD, Body 5.1x4.5mm, Pitch 0.65mm)
part A pins: 1 VCP "SYNC", 3 CP, 5 CN, 7 VIN "PVIN", 8 GND, 10 EN, 13 RO "INTB", 14 VOUT, 15 EPAD

## NCV68061
designator U?
NCV6806x family of Ideal Diode NMOS Driver
footprint TSOP-6 (TSOP-6, CASE 318G-02, ISSUE V)
pins: 1 NC, 2 GND, 3 EN, 4 D, 5 G, 6 S

## NCV81275
designator U?
8/7/6/5/4/3/2/1 Phase Buck Controller with PWM_VID and I2C Interface
footprint QFNW40 5x5, 0.4P
pins: 1 REFIN, 2 VREF, 3 VRAMP, 4 PWM8/SS, 5 PWM7/OCP, 6 PWM6/LPC1, 7 PWM5/LPC2, 8 PWM4/PHTH1, 9 PWM3/PHTH2, 10 PWM2/PHTH3, 11 PWM1/PHTH4, 12 DRON, 13 CSP8, 14 CSP7, 15 CSP6, 16 CSP5, 17 CSP4, 18 CSP3, 19 CSP2, 20 CSP1, 21 CSREF, 22 CSSUM, 23 CSCOMP, 24 ILIM, 25 IOUT, 26 LLTH/I2C, 27 FSW, 28 DIFF, 29 FB, 30 COMP, 31 VSP, 32 VSN, 33 VCC, 34 SDA, 35 SCL, 36 EN, 37 PSI, 38 PGOOD, 39 PWM_VID, 40 VID_BUFF, 41 PAD

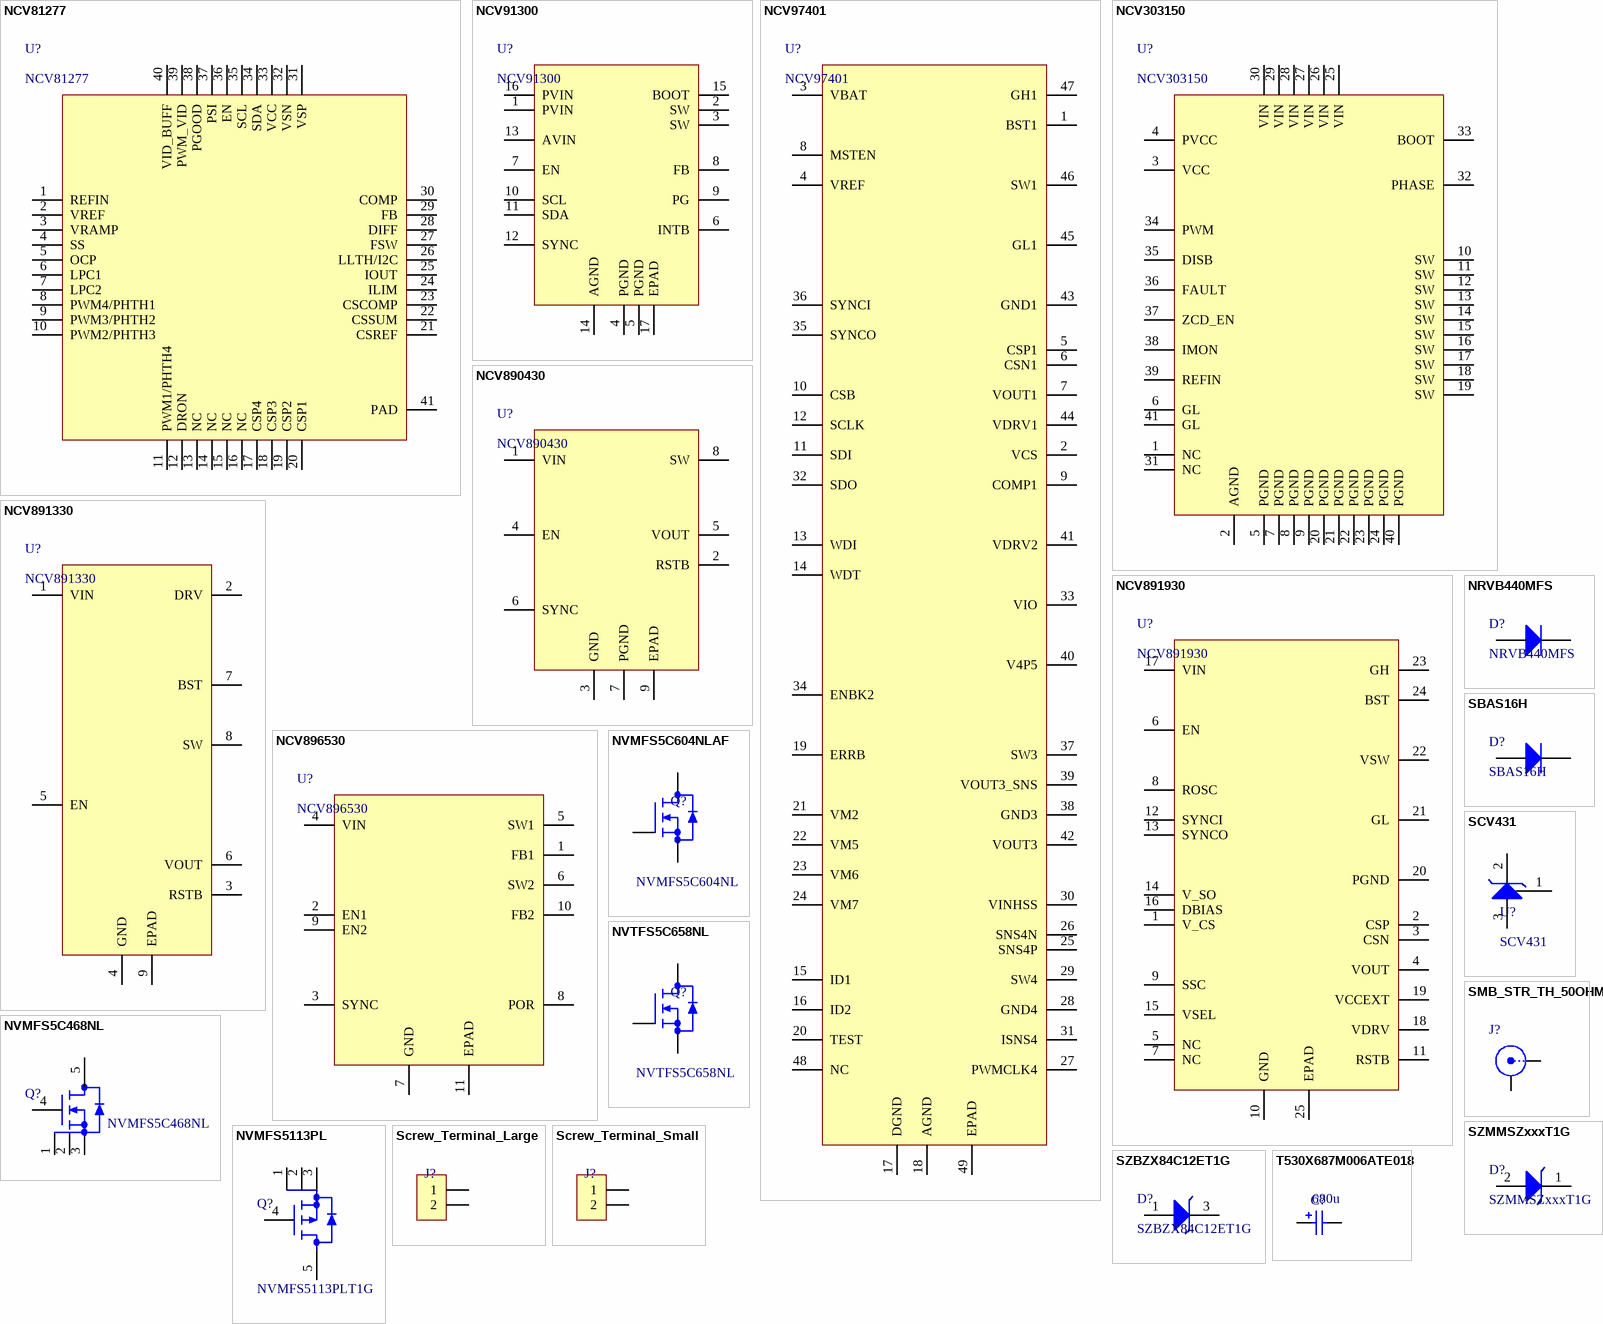
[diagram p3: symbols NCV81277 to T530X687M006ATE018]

## NCV81277
designator U?
4/3/2/1 Phase Buck Controller with PWM_VID and I2C Interface
footprint QFNW40 5x5, 0.4P
pins: 1 REFIN, 2 VREF, 3 VRAMP, 4 SS, 5 OCP, 6 LPC1, 7 LPC2, 8 PWM4/PHTH1, 9 PWM3/PHTH2, 10 PWM2/PHTH3, 11 PWM1/PHTH4, 12 DRON, 13 NC, 14 NC, 15 NC, 16 NC, 17 CSP4, 18 CSP3, 19 CSP2, 20 CSP1, 21 CSREF, 22 CSSUM, 23 CSCOMP, 24 ILIM, 25 IOUT, 26 LLTH/I2C, 27 FSW, 28 DIFF, 29 FB, 30 COMP, 31 VSP, 32 VSN, 33 VCC, 34 SDA, 35 SCL, 36 EN, 37 PSI, 38 PGOOD, 39 PWM_VID, 40 VID_BUFF, 41 PAD

## NCV91300
designator U?
Configurable 3.0 A Step Down Converter
footprint QFNQW16 3x3, 0.5P (QFNQW16 3x3, 0.5P, CASE 484AL, ISSUE A)
pins: 1 PVIN, 2 SW, 3 SW, 4 PGND, 5 PGND, 6 INTB, 7 EN, 8 FB, 9 PG, 10 SCL, 11 SDA, 12 SYNC, 13 AVIN, 14 AGND, 15 BOOT, 16 PVIN, 17 EPAD

## NCV97401
designator U?
Automotive Multi-Output Power / Management Unit with 1 Buck / Controller, 1 Boost Regulator, / HS/LED Driver, SPI / Communication, and Window / Watchdog
footprint QFN48 7x7, 0.5P (QFN48 7x7, 0.5P, CASE 485K-02, ISSUE D)
pins: 1 BST1, 2 VCS, 3 VBAT, 4 VREF, 5 CSP1, 6 CSN1, 7 VOUT1, 8 MSTEN, 9 COMP1, 10 CSB, 11 SDI, 12 SCLK, 13 WDI, 14 WDT, 15 ID1, 16 ID2, 17 DGND, 18 AGND, 19 ERRB, 20 TEST, 21 VM2, 22 VM5, 23 VM6, 24 VM7, 25 SNS4P, 26 SNS4N, 27 PWMCLK4, 28 GND4, 29 SW4, 30 VINHSS, 31 ISNS4, 32 SDO, 33 VIO, 34 ENBK2, 35 SYNCO, 36 SYNCI, 37 SW3, 38 GND3, 39 VOUT3_SNS, 40 V4P5, 41 VDRV2, 42 VOUT3, 43 GND1, 44 VDRV1, 45 GL1, 46 SW1, 47 GH1, 48 NC, 49 EPAD

## NCV303150
designator U?
Smart Power Stage (SPS) Module with Integrated Thermal Warning, Thermal Shutdown and Current Monitoring
footprint PQFN39 5x6, 0.45P (PQFN39 5x6, 0.45P, CASE 483BF, ISSUE O)
pins: 1 NC, 2 AGND, 3 VCC, 4 PVCC, 5 PGND, 6 GL, 7 PGND, 8 PGND, 9 PGND, 10 SW, 11 SW, 12 SW, 13 SW, 14 SW, 15 SW, 16 SW, 17 SW, 18 SW, 19 SW, 20 PGND, 21 PGND, 22 PGND, 23 PGND, 24 PGND, 25 VIN, 26 VIN, 27 VIN, 28 VIN, 29 VIN, 30 VIN, 31 NC, 32 PHASE, 33 BOOT, 34 PWM, 35 DISB, 36 FAULT, 37 ZCD_EN, 38 IMON, 39 REFIN, 40 PGND, 41 GL

## NCV890430
designator U?
0.6 A 2 MHz 100% Duty Cycle Step‐Down Synchronous Regulator for Automotive
footprint DFN8 3x3 0.65P (DFN8 3x3 0.65P, CASE 506CS, Issue O)
pins: 1 VIN "PVIN", 2 RSTB "INTB", 3 GND, 4 EN, 5 VOUT, 6 SYNC, 7 PGND, 8 SW, 9 EPAD

## NCV891330
designator U?
3 A, 2 MHz Low-IQ Dual-Mode Step-Down Regulator for Automotive
footprint SOIC-8 EP (SOIC-8 EP, CASE 751AC Issue C,, Body 4.90x3.90mm, Pitch 1.27mm, Thermal Pad 3.20x2.51mm, IPC Medium Density)
pins: 1 VIN, 2 DRV, 3 RSTB, 4 GND, 5 EN, 6 VOUT, 7 BST, 8 SW, 9 EPAD

## NCV891930
designator U?
Low Quiescent Current 2 MHz Automotive Synchronous Buck Controller
footprint QFNW24 4x4 0.5P (QFNW, 24-Leads, Body 4.00x4.00mm, Pitch 0.50mm, Thermal Pad 2.80x2.80mm, IPC Medium Density)
pins: 1 V_CS, 2 CSP, 3 CSN, 4 VOUT, 5 NC, 6 EN, 7 NC, 8 ROSC, 9 SSC, 10 GND, 11 RSTB, 12 SYNCI, 13 SYNCO, 14 V_SO, 15 VSEL, 16 DBIAS, 17 VIN, 18 VDRV, 19 VCCEXT, 20 PGND, 21 GL, 22 VSW, 23 GH, 24 BST, 25 EPAD

## NCV896530
designator U?
2 Channel DC-DC Step Down Converter
footprint DFN10 3x3 0.5P (485C) (DFN10 3x3 0.5P, CASE (485C, ISSUE E)
pins: 1 FB1, 2 EN1, 3 SYNC, 4 VIN, 5 SW1, 6 SW2, 7 GND, 8 POR, 9 EN2, 10 FB2, 11 EPAD

## NRVB440MFS
designator D?
NRVB440MFS; 4.0A/40V; DFN5 5x6, 1.27P (SO-8 FL); On Semiconductor
footprint DFN5 5x6, 1.27P (SO-8FL)
pins: 1 A, 2 A hidden, 2 A, 3 A hidden, 3 A, 5 C

## NVMFS5C468NL
designator Q?, comment value NVMFS5C468NL  (hidden comment: NVMFS5C468NLWFT1GW)
NVMFS5C468NLWFT1GW; NMOS; 40V/37A/28W, 10.3mOhm, 175°C; SO-8FL; ON Semiconductor; Signature Author: Hukel; Substitution Allowed: Yes
footprint DFN5 5x6, 1.27P (SO-8FL)
pins: 1 S, 2 S, 3 S, 4 G, 5 D

## NVMFS5C604NLAF
designator Q?  value NVMFS5C604NL  (hidden comment: NVMFS5C604NLAF)
NVMFS5C604NL; NMOS; 60V/287A/200W, 1.2mOhm, 175°C; LFPAK-8; ON Semiconductor; Signature Author: Nagy; Substitution Allowed: Yes
footprint LFPAK8 (5-Pads, Body 5.55x6.01mm (max), IPC Low Density)
pins: 1 S, 2 S, 3 S, 4 G, 5 D

## NVMFS5113PL
designator Q?, comment NVMFS5113PLT1G
NVMFS5113PL, P-Type Power MOSFET; NMOS; -60V/-64A/150W, 14mOhm, 175°C; SO-8FL; ON Semiconductor; Signature Author: Hukel; Substitution Allowed: Yes
footprint DFN5 5x6, 1.27P (SO-8FL)
pins: 1 S, 2 S, 3 S, 4 G, 5 D

## NVTFS5C658NL
designator Q?
NVTFS5C658NL; NMOS; 60V/109A/114W, 5.0mOhm, 175°C; u8FL; ON Semiconductor; Signature Author: Nagy; Substitution Allowed: Yes
footprint u8FL (5-Pads, Body 3.30x3.30mm (max), IPC Low Density)
pins: 1 S, 2 S, 3 S, 4 G, 5 D

## SBAS16H
designator D?
SBAS16H; 1.0A/100V; SOD-323; On Semiconductor
footprint SOD-323 (SOD323, 2-Leads, Body 1.25x1.70mm, IPC Medium Density)
pins: 1 C, 2 A

## Screw_Terminal_Large
designator J?, comment ED120/2S  (value not drawn)
Large Screw Terminal,  TERM BLK 2P SIDE ENT 5.08MM PCB; Manufacturer: Samtec; Signature Author: Zemanovic; Value/Rating: TSW-102-07-G-S; Value: TSW-102-07-G-S; Substitution Allowed: Yes
footprint ED120/2DS (Large Screw Terminal)
pins: 1, 2

## Screw_Terminal_Small
designator J?, comment ED555/2S  (value not drawn)
Small Screw Terminal,  TERM BLK 2POS SIDE ENT 3.5MM PCB; Manufacturer: Samtec; Signature Author: Zemanovic; Value/Rating: TSW-102-07-G-S; Value: TSW-102-07-G-S; Substitution Allowed: Yes
pins: 1, 2

## SCV431
designator U?
Low Voltage Precision Adjustable Shunt Regulator
footprint SOT-23 (TO-236) (SOT-23 (TO-236), CASE 318-08, Issue AS)
pins: 1 R, 2 K, 3 A

## SMB_STR_TH_50OHM
designator J?  (value not drawn)
SMB JACK STR; 50 OHM; TH; 1-1337482-0; Manufacturer: TE Connectivity; Signature Author: Zemanovic; Substitution Allowed: Yes
footprint SMB_STR_TH
pins: 1, 2

## SZBZX84C12ET1G
designator D?
SZBZX84CxxET1G Zener Diode Family
footprint SOT-23 (TO-236) (SOT-23 (TO-236), CASE 318-08, Issue AS)
pins: 1 A, 2 NC hidden, 3 C

## SZMMSZxxxT1G
designator D?
SZMMSZxxxT1G Zener Diode Family
footprint SOD-123 (SOD, 2-Leads, Body 2.69x1.6mm)
pins: 1 C, 2 A

## T530X687M006ATE018
designator C?  value 680u  (hidden comment: T530X687M006ATE018)
680uF; 6.3V; Tantalum; 20%; 7343; T530X687M006ATE018; KEMET; Signature Author: Hukel; Substitution Allowed: Yes; Value/Rating: 680u/6.3V
footprint 7343-43 (7343-43, Molded Capacitor, 2-Leads, Body 7.30x4.30mm, IPC Medium Density)
pins: 1, 2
